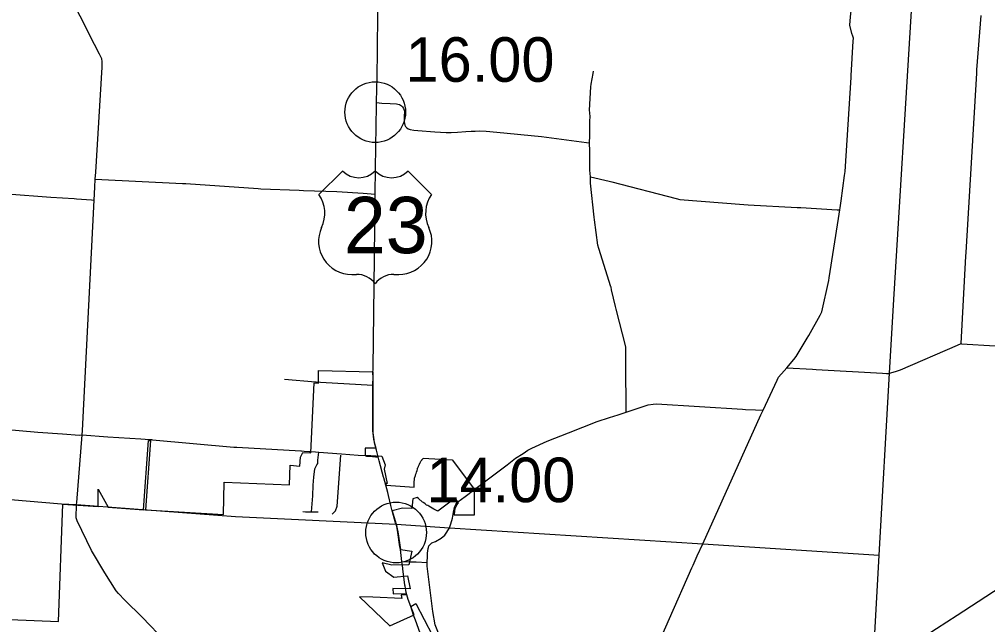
# Model space of a CAD drawing. Extents: x 1729596 to 1934326, y 644115 to 911751.
# Drawn here: x 1799698 to 1823628, y 845758 to 860705 of the extents above; entities that cross this region are included whole.
import ezdxf

# ---------------------------------------------------------------- set-up
doc = ezdxf.new("R2010")
doc.units = 0
for name, color, linetype in [('Default', 7, 'Continuous'), ('GM_X_City_Street', 7, 'Continuous'), ('GM_X_Corporation', 7, 'Continuous'), ('GM_X_County_Road', 7, 'Continuous'), ('GM_X_Township', 7, 'Continuous'), ('GM_X_Township_Road', 7, 'Continuous'), ('GM_X_US_Route', 7, 'Continuous'), ('GM_X_US_Shield', 7, 'Continuous')]:
    doc.layers.add(name, color=color, linetype=linetype)

msp = doc.modelspace()

# ---------------------------------------------------------------- linework, layer by layer
at = {"layer": 'Default'}
for centre in [(1808492, 858414), (1809009, 848032)]:
    msp.add_circle(centre, 750, dxfattribs=at)
at = {"layer": 'GM_X_City_Street'}
for points in [[(1807140, 851748), (1808437, 851668)], [(1806882, 850032), (1807018, 850025), (1807099, 850018), (1807656, 849972), (1808075, 849940), (1808241, 849934), (1808275, 849918), (1808332, 849915), (1808428, 849910), (1808503, 849903), (1808563, 849901)], [(1806917, 848547), (1806947, 848935), (1806958, 849198), (1806978, 849396), (1807000, 849604), (1807027, 849656), (1807053, 849702), (1807070, 849736), (1807078, 849816), (1807099, 850018)], [(1807429, 848485), (1807510, 848566), (1807549, 848686), (1807646, 849939)], [(1810538, 848793), (1810714, 848923), (1810919, 849078)], [(1803391, 844506), (1803386, 844699), (1803411, 844996), (1803417, 845098), (1803416, 845170), (1803320, 845337), (1802730, 845945), (1802308, 846362), (1802144, 846526), (1802086, 846596), (1801814, 847037), (1801477, 847586), (1801128, 848318), (1801102, 848399), (1801113, 848728), (1801117, 848771)], [(1806705, 848555), (1806769, 848544), (1806917, 848547), (1807079, 848543)], [(1809152, 847319), (1809360, 847312)]]:
    msp.add_lwpolyline(points, dxfattribs=at)
at = {"layer": 'GM_X_Corporation'}
msp.add_lwpolyline([(1798053, 845944), (1800661, 845836), (1800775, 848735), (1801643, 848675), (1801648, 849101), (1801894, 848657), (1802762, 848594), (1802886, 850307), (1802936, 850304), (1802812, 848592), (1804746, 848481), (1804763, 849272), (1806371, 849213), (1806387, 849693), (1806631, 849675), (1806647, 849895), (1806700, 850012), (1806903, 849998), (1806985, 851728), (1807088, 851722), (1807090, 852031), (1808433, 851997), (1808431, 850641), (1808436, 850498), (1808449, 850376), (1808470, 850255), (1808504, 850114), (1808243, 850118), (1808241, 849941), (1808654, 849917), (1808737, 849703), (1808710, 849595), (1808790, 849247), (1808740, 849246), (1808759, 849201), (1809456, 849154), (1809458, 849294), (1809459, 849307), (1809460, 849322), (1809461, 849340), (1809462, 849349), (1809463, 849350), (1809464, 849362), (1809467, 849379), (1809470, 849393), (1809472, 849401), (1809475, 849407), (1809476, 849411), (1809477, 849414), (1809480, 849420), (1809484, 849431), (1809486, 849436), (1809491, 849454), (1809497, 849474), (1809502, 849491), (1809511, 849522), (1809527, 849568), (1809534, 849595), (1809537, 849605), (1809541, 849618), (1809544, 849626), (1809546, 849632), (1809551, 849644), (1809560, 849662), (1809565, 849673), (1809578, 849708), (1809583, 849720), (1809588, 849729), (1809593, 849738), (1809606, 849764), (1809611, 849773), (1809615, 849782), (1809621, 849792), (1809623, 849795), (1809628, 849801), (1809637, 849812), (1809641, 849818), (1809647, 849826), (1809654, 849838), (1809659, 849845), (1809666, 849853), (1809681, 849870), (1810394, 849826), (1810945, 849097), (1810937, 849092), (1810939, 848462), (1810440, 848460), (1810456, 848543), (1810463, 848575), (1810469, 848607), (1810479, 848644), (1810492, 848682), (1810515, 848723), (1810542, 848756), (1810552, 848765), (1810465, 848883), (1810105, 848611), (1810039, 848558), (1809945, 848607), (1809817, 848685), (1809792, 848696), (1809763, 848711), (1809726, 848740), (1809697, 848764), (1809685, 848772), (1809662, 848785), (1809560, 848875), (1809530, 848899), (1809421, 848861), (1809398, 848625), (1809168, 848637), (1808914, 848571), (1809012, 848241), (1809052, 848053), (1809117, 847610), (1809395, 847571), (1809325, 847237), (1808906, 847223), (1808660, 847284), (1808750, 847079), (1808950, 846927), (1809294, 846961), (1809355, 846639), (1808928, 846653), (1808933, 846518), (1809251, 846529), (1809259, 846496), (1809133, 846487), (1809149, 846407), (1808433, 846432), (1808107, 846444), (1808850, 845724), (1809453, 845996), (1809370, 846205), (1809495, 846276), (1809904, 845490)], dxfattribs=at)
at = {"layer": 'GM_X_County_Road'}
for points in [[(1801567, 856755), (1801567, 856755), (1801584, 856930), (1801742, 859524), (1801746, 859662), (1801732, 859727), (1801677, 859846), (1801556, 860087), (1800489, 862190), (1800471, 862240), (1800469, 862342), (1800776, 866006), (1800811, 866452), (1800848, 866888), (1800911, 867730), (1800965, 868323), (1801008, 868838), (1801046, 869299), (1801092, 869835), (1801238, 871613)], [(1819979, 856052), (1820004, 856221), (1820093, 856849), (1820106, 856948), (1820253, 859267), (1820256, 859321), (1820308, 860164), (1820312, 860243), (1820295, 860293), (1820272, 860358), (1820219, 860562), (1820238, 860767), (1820341, 861658), (1820408, 862232), (1820454, 862755), (1820524, 864057), (1820528, 864114), (1820480, 864265), (1820462, 864324)], [(1813792, 857659), (1813794, 857827), (1813800, 858197), (1813802, 858295), (1813794, 858400), (1813790, 858459), (1813824, 859039), (1813828, 859109), (1813877, 859368), (1813888, 859424)], [(1808526, 858649), (1808657, 858638), (1808859, 858626), (1809019, 858618), (1809052, 858615), (1809095, 858599), (1809143, 858567), (1809166, 858544), (1809192, 858504), (1809208, 858460), (1809213, 858422), (1809211, 858321), (1809207, 858185), (1809213, 858132), (1809225, 858094), (1809243, 858063), (1809274, 858027), (1809305, 858005), (1809359, 857983), (1809445, 857973), (1809547, 857964), (1809965, 857932), (1810245, 857914), (1810373, 857908), (1810529, 857918), (1810728, 857939), (1810862, 857945), (1810963, 857947), (1811066, 857950), (1811236, 857941), (1811500, 857918), (1812600, 857811), (1813718, 857665), (1813792, 857659)], [(1813810, 856819), (1813800, 856979), (1813794, 857454), (1813792, 857659)], [(1801549, 856244), (1801549, 856244), (1801565, 856560), (1801567, 856755)], [(1801567, 856755), (1803730, 856654), (1803812, 856649), (1805603, 856528), (1805663, 856523)], [(1813810, 856819), (1814272, 856708), (1814342, 856691), (1815928, 856285), (1816023, 856260), (1817602, 856132), (1817706, 856124), (1818919, 856063), (1819010, 856058), (1819906, 856004), (1819971, 856000)], [(1814317, 854102), (1814022, 855049), (1813998, 855126), (1813913, 855754), (1813904, 855818), (1813815, 856658), (1813810, 856819)], [(1801256, 850553), (1801549, 856244)], [(1816452, 847455), (1816586, 847751), (1818021, 850937), (1818081, 851052), (1818426, 851791), (1818463, 851867), (1818600, 852027), (1818667, 852103), (1818835, 852306), (1818895, 852378), (1819166, 852831), (1819205, 852895), (1819487, 853403), (1819531, 853481), (1819699, 854255), (1819715, 854325), (1819940, 855787), (1819971, 856000), (1819979, 856052)], [(1814694, 851004), (1814695, 851266), (1814689, 851950), (1814688, 852505), (1814683, 852620), (1814444, 853547), (1814429, 853618), (1814335, 854030), (1814321, 854092), (1814317, 854102)], [(1810919, 849078), (1811263, 849337), (1811751, 849702), (1811961, 849865), (1812147, 849988), (1812264, 850069), (1812359, 850119), (1812745, 850286), (1813271, 850498), (1813977, 850777), (1814286, 850877), (1814495, 850939), (1814694, 851004)], [(1801117, 848771), (1801250, 850449), (1801256, 850553)], [(1809807, 847663), (1809821, 847704), (1809847, 847739), (1809889, 847777), (1809981, 847807), (1810120, 847890), (1810211, 847966), (1810266, 848041), (1810328, 848152), (1810364, 848247), (1810399, 848390), (1810425, 848536), (1810448, 848647), (1810483, 848724), (1810516, 848777), (1810538, 848793)], [(1809360, 847312), (1809508, 847308), (1809777, 847295), (1809775, 847335), (1809781, 847406), (1809787, 847526), (1809799, 847641), (1809807, 847663)], [(1814101, 842164), (1814760, 843649), (1815210, 844662), (1816320, 847160), (1816351, 847229), (1816426, 847398), (1816452, 847455)]]:
    msp.add_lwpolyline(points, dxfattribs=at)
at = {"layer": 'GM_X_Township'}
for points in [[(1820182, 834021), (1820274, 835623), (1820357, 837080), (1820411, 838018), (1820789, 844650), (1820950, 847472), (1821204, 851968), (1821306, 853784), (1821743, 860915)], [(1794528, 849265), (1800736, 848740), (1801113, 848728), (1805038, 848430), (1809012, 848241), (1810328, 848152), (1816586, 847751), (1820950, 847472)]]:
    msp.add_lwpolyline(points, dxfattribs=at)
at = {"layer": 'GM_X_Township_Road'}
for points in [[(1822973, 852697), (1823090, 854855), (1823095, 854950), (1823360, 859378), (1823364, 859462), (1823464, 860797)], [(1795090, 856488), (1796016, 856428), (1796449, 856346), (1796551, 856339), (1796604, 856337), (1796665, 856335), (1796771, 856339), (1796829, 856341), (1797357, 856367), (1797448, 856371), (1797816, 856403), (1797914, 856411), (1798495, 856434), (1798591, 856437), (1798633, 856451), (1800371, 856321), (1800474, 856313), (1801054, 856281), (1801112, 856277), (1801481, 856249), (1801549, 856244)], [(1805663, 856523), (1806613, 856487), (1806716, 856483), (1807543, 856452), (1808194, 856410), (1808493, 856392)], [(1821238, 851978), (1821378, 852020), (1821474, 852048), (1822880, 852657), (1822973, 852697), (1822981, 852696), (1823816, 852647), (1823896, 852643), (1826953, 852461), (1827020, 852457), (1827766, 852423)], [(1818667, 852103), (1819299, 852064), (1819393, 852058), (1821027, 851968), (1821128, 851962), (1821176, 851960), (1821204, 851968), (1821237, 851978), (1821238, 851978)], [(1794724, 851732), (1794738, 851729), (1794935, 851656), (1795122, 851581), (1795265, 851527), (1796002, 851268), (1796641, 851079), (1797379, 850870), (1797893, 850723), (1797966, 850705), (1798085, 850695), (1798763, 850635), (1800156, 850514), (1800763, 850469), (1801182, 850439), (1801250, 850449)], [(1806254, 851821), (1807013, 851757)], [(1807013, 851757), (1807030, 851756), (1807140, 851748)], [(1814694, 851004), (1815165, 851158), (1815240, 851182), (1815362, 851206), (1815440, 851209), (1817571, 851075), (1817642, 851071), (1817892, 851059), (1818081, 851052)], [(1801250, 850449), (1801881, 850399), (1802703, 850348), (1802910, 850330), (1802935, 850329)], [(1802935, 850329), (1802961, 850327), (1802988, 850325)], [(1802988, 850325), (1804995, 850144), (1805070, 850138), (1806658, 850048), (1806671, 850048)], [(1806671, 850048), (1806740, 850044), (1806868, 850033), (1806882, 850032)], [(1811145, 843912), (1811099, 843915), (1810940, 843921), (1810776, 843956), (1810680, 844009), (1810636, 844058), (1810436, 844399), (1810264, 844699), (1810200, 844927), (1810124, 845291), (1810078, 845492), (1810023, 845627), (1809977, 845754), (1809919, 846084), (1809777, 847204), (1809777, 847295)]]:
    msp.add_lwpolyline(points, dxfattribs=at)
at = {"layer": 'GM_X_US_Route'}
for points in [[(1808531, 859016), (1808538, 859249), (1808549, 859969), (1808564, 861690), (1808584, 862855), (1808592, 863349), (1808593, 863493)], [(1808510, 857628), (1808515, 857996), (1808526, 858649), (1808531, 858995), (1808531, 859016)], [(1808437, 851954), (1808441, 852097), (1808474, 854817), (1808493, 856392), (1808501, 857014), (1808510, 857555), (1808510, 857628)], [(1808516, 850092), (1808496, 850167), (1808459, 850341), (1808448, 850411), (1808434, 850552), (1808431, 850641), (1808433, 851249), (1808431, 851273), (1808433, 851468), (1808437, 851668), (1808439, 851882), (1808437, 851954)], [(1808563, 849901), (1808563, 849901), (1808522, 850068), (1808516, 850092)], [(1808697, 849401), (1808592, 849800), (1808563, 849901)], [(1808752, 849202), (1808703, 849381), (1808697, 849401)], [(1808821, 848950), (1808803, 849024), (1808752, 849202)], [(1808921, 848545), (1808914, 848571), (1808882, 848700), (1808821, 848950)], [(1809104, 847681), (1809054, 848036), (1809027, 848179), (1809012, 848241), (1809010, 848249), (1808995, 848272), (1808921, 848545)], [(1815985, 842997), (1816140, 843045), (1816516, 843159), (1818004, 843604), (1819466, 844036), (1819970, 844186), (1820078, 844226), (1820154, 844261), (1820230, 844302), (1820378, 844395), (1820678, 844582), (1820789, 844650), (1821371, 845021), (1821564, 845146), (1821850, 845326), (1822366, 845660), (1822875, 845990), (1823392, 846332), (1823964, 846703), (1824557, 847070), (1825025, 847354), (1825562, 847681), (1826103, 848010), (1826523, 848267)], [(1809164, 847216), (1809152, 847319), (1809114, 847613), (1809104, 847681)], [(1809182, 847063), (1809164, 847216)], [(1809230, 846706), (1809225, 846732), (1809197, 846941), (1809182, 847063)], [(1809249, 846605), (1809230, 846706)], [(1809259, 846555), (1809249, 846605)], [(1809486, 845872), (1809442, 845995), (1809370, 846205), (1809307, 846378), (1809259, 846553), (1809259, 846555)], [(1809906, 844822), (1809859, 844918), (1809769, 845106), (1809684, 845316), (1809486, 845872)]]:
    msp.add_lwpolyline(points, dxfattribs=at)
at = {"layer": 'GM_X_US_Shield'}
for p, q in [((1807680, 856960), (1807100, 856380)), ((1807680, 856960), (1807100, 856380)), ((1809884, 856380), (1809304, 856960)), ((1809884, 856380), (1809304, 856960)), ((1807912, 854408), (1808028, 854408)), ((1807912, 854408), (1808028, 854408)), ((1808956, 854408), (1809072, 854408)), ((1808956, 854408), (1809072, 854408))]:
    msp.add_line(p, q, dxfattribs=at)
for centre, radius, start, end in [((1808086, 857375), 580, 225.573, 314.427), ((1808086, 857375), 580, 225.573, 314.427), ((1808898, 857375), 580, 225.573, 314.427), ((1808898, 857375), 580, 225.573, 314.427), ((1806435, 855915), 812, 334.5471, 35.0009), ((1806435, 855915), 812, 334.5471, 35.0009), ((1810549, 855915), 812, 144.9991, 205.4529), ((1810549, 855915), 812, 144.9991, 205.4529), ((1807903, 855220), 812, 154.8319, 270.6383), ((1807903, 855220), 812, 154.8319, 270.6383), ((1809081, 855220), 812, 269.3617, 25.1681), ((1809081, 855220), 812, 269.3617, 25.1681), ((1808028, 853828), 580, 36.8699, 90), ((1808028, 853828), 580, 36.8699, 90), ((1808956, 853828), 580, 90, 143.1301), ((1808956, 853828), 580, 90, 143.1301)]:
    msp.add_arc(centre, radius, start, end, dxfattribs=at)

# ---------------------------------------------------------------- texts
at = {"layer": 'Default'}
for s, p in [('16.00', (1809242, 859164)), ('14.00', (1809759, 848782))]:
    msp.add_text(s, height=1100, dxfattribs=at).set_placement(p)
at = {"layer": 'GM_X_US_Shield'}
msp.add_text('23', height=1392.2, dxfattribs=at).set_placement((1807717, 854930))
msp.add_text('23', height=1392.2, dxfattribs=at).set_placement((1807717, 854930))

doc.saveas('drawing.dxf')
